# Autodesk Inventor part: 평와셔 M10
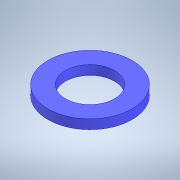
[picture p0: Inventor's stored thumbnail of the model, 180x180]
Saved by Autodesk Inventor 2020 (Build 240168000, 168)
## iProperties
Created: 2024-04
Part Number: 평와셔 M10
Material: 강철, 연강
Document SubType Name: Modeling
Designer: oem
Density: 7.86 g/cm^3
Appearance: 기본값
Author: jhkim
Sending System: Autodesk Inventor 2025
Preprocessor: ST-DEVELOPER v20
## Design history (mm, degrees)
feature "솔리드1"
node "솔리드2"
